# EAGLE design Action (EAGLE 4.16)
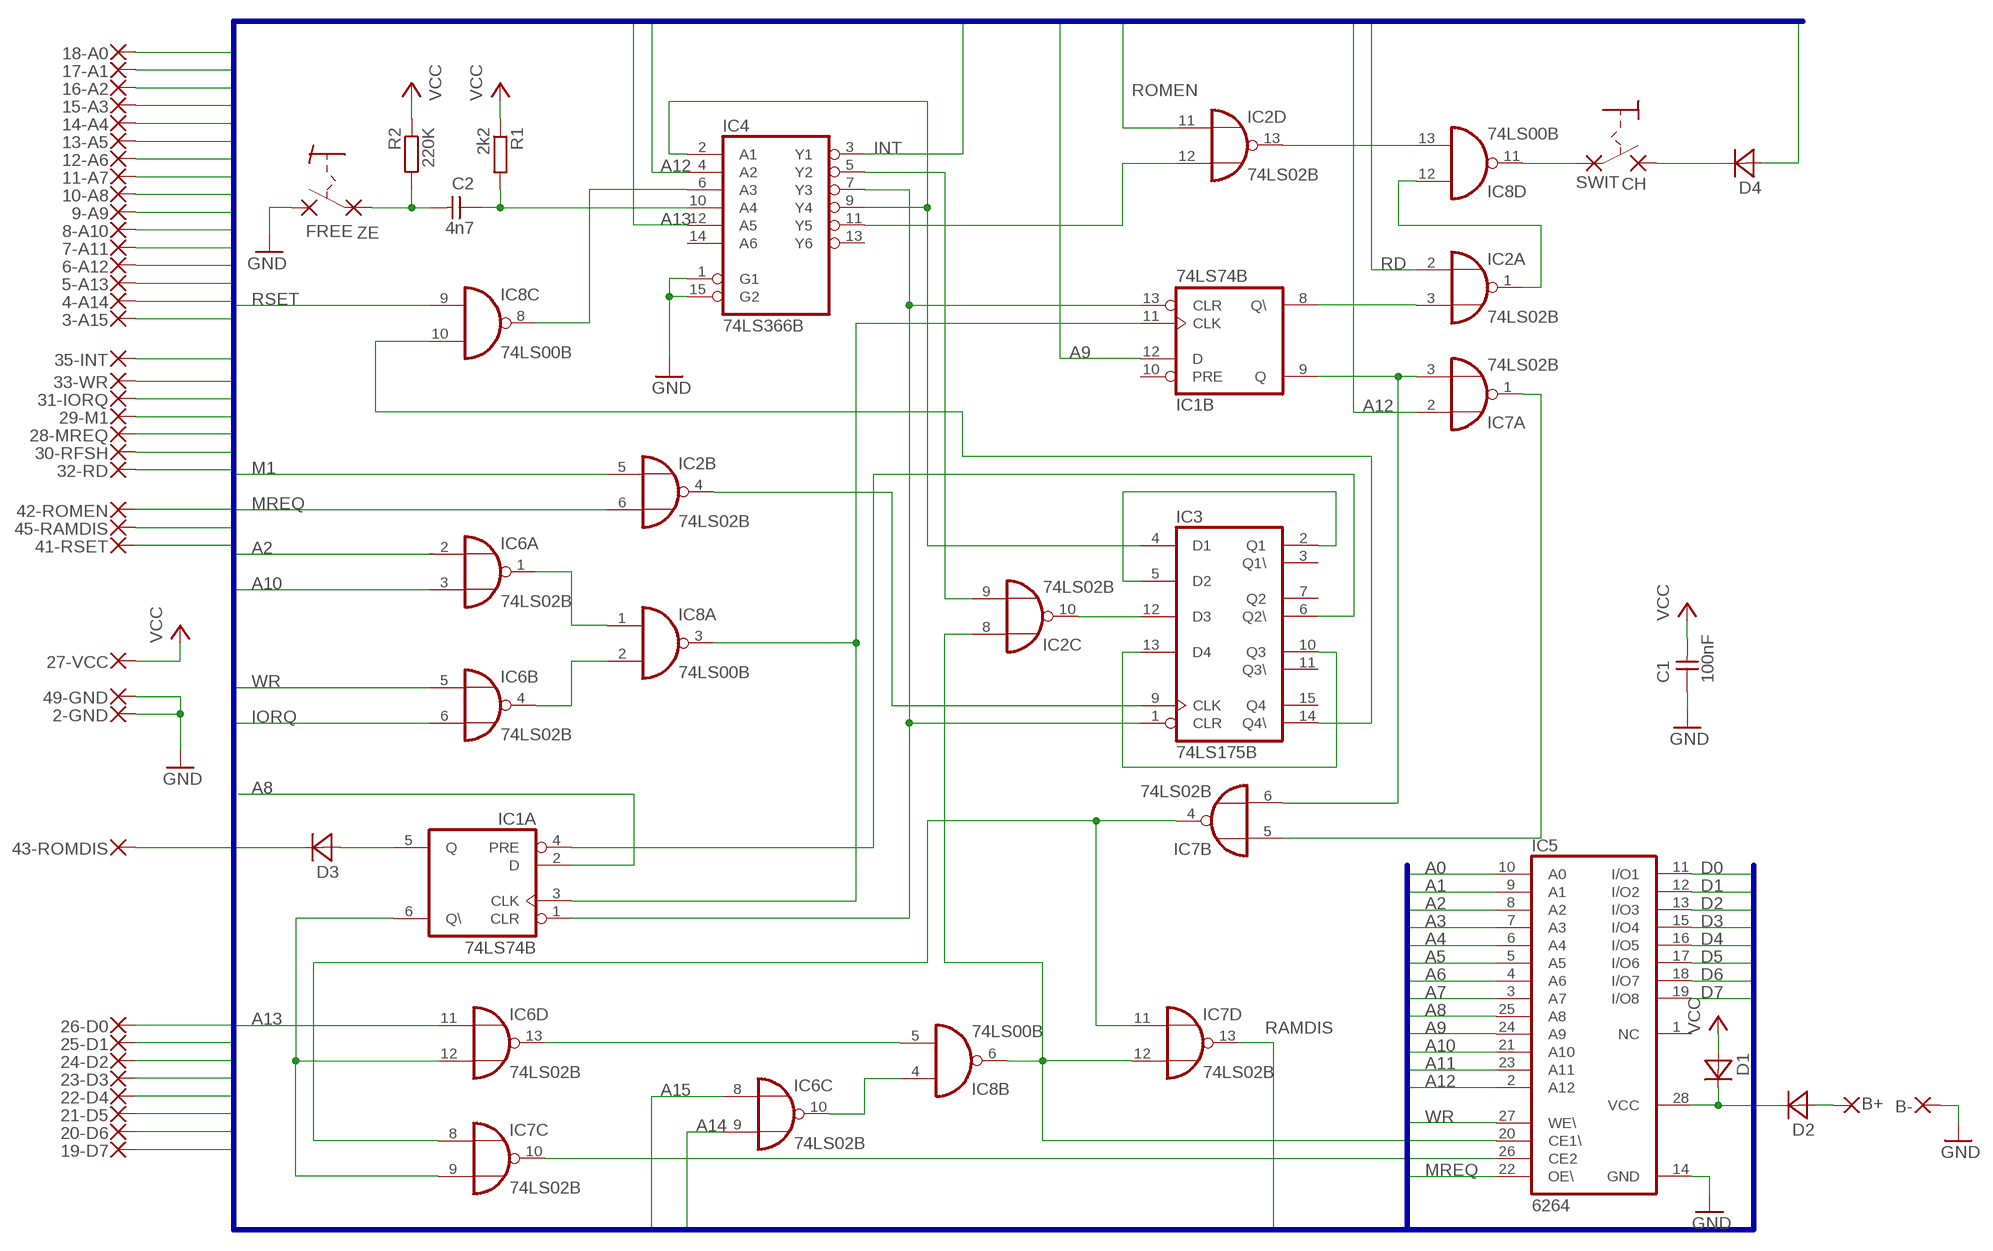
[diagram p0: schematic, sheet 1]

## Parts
2-GND  1,27-REDONDO0.8  [1,27/0,8-REDONDO]
3-A15  1,27-REDONDO0.8  [1,27/0,8-REDONDO]
4-A14  1,27-REDONDO0.8  [1,27/0,8-REDONDO]
5-A13  1,27-REDONDO0.8  [1,27/0,8-REDONDO]
6-A12  1,27-REDONDO0.8  [1,27/0,8-REDONDO]
7-A11  1,27-REDONDO0.8  [1,27/0,8-REDONDO]
8-A10  1,27-REDONDO0.8  [1,27/0,8-REDONDO]
9-A9  1,27-REDONDO0.8  [1,27/0,8-REDONDO]
10-A8  1,27-REDONDO0.8  [1,27/0,8-REDONDO]
11-A7  1,27-REDONDO0.8  [1,27/0,8-REDONDO]
12-A6  1,27-REDONDO0.8  [1,27/0,8-REDONDO]
13-A5  1,27-REDONDO0.8  [1,27/0,8-REDONDO]
14-A4  1,27-REDONDO0.8  [1,27/0,8-REDONDO]
15-A3  1,27-REDONDO0.8  [1,27/0,8-REDONDO]
16-A2  1,27-REDONDO0.8  [1,27/0,8-REDONDO]
17-A1  1,27-REDONDO0.8  [1,27/0,8-REDONDO]
18-A0  1,27-REDONDO0.8  [1,27/0,8-REDONDO]
19-D7  1,27-REDONDO0.8  [1,27/0,8-REDONDO]
20-D6  1,27-REDONDO0.8  [1,27/0,8-REDONDO]
21-D5  1,27-REDONDO0.8  [1,27/0,8-REDONDO]
22-D4  1,27-REDONDO0.8  [1,27/0,8-REDONDO]
23-D3  1,27-REDONDO0.8  [1,27/0,8-REDONDO]
24-D2  1,27-REDONDO0.8  [1,27/0,8-REDONDO]
25-D1  1,27-REDONDO0.8  [1,27/0,8-REDONDO]
26-D0  1,27-REDONDO0.8  [1,27/0,8-REDONDO]
27-VCC  1,27-REDONDO0.8  [1,27/0,8-REDONDO]
28-MREQ  1,27-REDONDO0.8  [1,27/0,8-REDONDO]
29-M1  1,27-REDONDO0.8  [1,27/0,8-REDONDO]
30-RFSH  1,27-REDONDO0.8  [1,27/0,8-REDONDO]
31-IORQ  1,27-REDONDO0.8  [1,27/0,8-REDONDO]
32-RD  1,27-REDONDO0.8  [1,27/0,8-REDONDO]
33-WR  1,27-REDONDO0.8  [1,27/0,8-REDONDO]
35-INT  1,27-REDONDO0.8  [1,27/0,8-REDONDO]
41-RSET  1,27-REDONDO0.8  [1,27/0,8-REDONDO]
42-ROMEN  1,27-REDONDO0.8  [1,27/0,8-REDONDO]
43-ROMDIS  1,27-REDONDO0.8  [1,27/0,8-REDONDO]
45-RAMDIS  1,27-REDONDO0.8  [1,27/0,8-REDONDO]
49-GND  1,27-REDONDO0.8  [1,27/0,8-REDONDO]
B+  1,27-CUADRADO0.8  [1,27/0,8-CUADRADO]
B-  1,27-CUADRADO0.8  [1,27/0,8-CUADRADO]
C1  100nF  CAPNP-10  [C-10]
C2  4n7  CAPNP-10  [C-10]
CH  1,6/0,8  [1,6/0,8]
D1  DIODE-10/2  [D-10/2]
D2  DIODE-10/2  [D-10/2]
D3  DIODE-10/2  [D-10/2]
D4  DIODE-12,5/2  [D-12,5/2]
FREE  1,6/0,8  [1,6/0,8]
IC1  74LS74B  [DIL14-B]
IC2  74LS02B  [DIL14-B]
IC3  74LS175B  [DIL16-B]
IC4  74LS366B  [DIL16-B]
IC5  6264  4364CB  [DIL28-6B]
IC6  74LS02B  [DIL14-B]
IC7  74LS02B  [DIL14-B]
IC8  74LS00B  [DIL14-B]
R1  2k2  R-EU_0207/10  [0207/10]
R2  220K  R-EU_0207/10  [0207/10]
SWIT  1,6/0,8  [1,6/0,8]
ZE  1,6/0,8  [1,6/0,8]

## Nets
A0: 18-A0.1(P) IC5.10(A0)
A1: 17-A1.1(P) IC5.9(A1)
A2: 16-A2.1(P) IC5.8(A2) IC6.2(A:I0)
A3: 15-A3.1(P) IC5.7(A3)
A4: 14-A4.1(P) IC5.6(A4)
A5: 13-A5.1(P) IC5.5(A5)
A6: 12-A6.1(P) IC5.4(A6)
A7: 11-A7.1(P) IC5.3(A7)
A8: 10-A8.1(P) IC1.2(A:D) IC5.25(A8)
A9: 9-A9.1(P) IC1.12(B:D) IC5.24(A9)
A10: 8-A10.1(P) IC5.21(A10) IC6.3(A:I1)
A11: 7-A11.1(P) IC5.23(A11)
A12: 6-A12.1(P) IC4.4(A2) IC5.2(A12) IC7.2(A:I0)
A13: 5-A13.1(P) IC4.12(A5) IC6.11(D:I0)
A14: 4-A14.1(P) IC6.9(C:I1)
A15: 3-A15.1(P) IC6.8(C:I0)
D0: 26-D0.1(P) IC5.11(I/O1)
D1: 25-D1.1(P) IC5.12(I/O2)
D2: 24-D2.1(P) IC5.13(I/O3)
D3: 23-D3.1(P) IC5.15(I/O4)
D4: 22-D4.1(P) IC5.16(I/O5)
D5: 21-D5.1(P) IC5.17(I/O6)
D6: 20-D6.1(P) D4.P$1(A) IC5.18(I/O7)
D7: 19-D7.1(P) IC5.19(I/O8)
GND: 2-GND.1(P) 49-GND.1(P) B-.P$1(P) C1.1 IC4.1(G1) IC4.15(G2) IC5.14(GND) ZE.1(P)
INT: 35-INT.1(P) IC4.3(Y1)
IORQ: 31-IORQ.1(P) IC6.6(B:I1)
M1: 29-M1.1(P) IC2.5(B:I0)
MREQ: 28-MREQ.1(P) IC2.6(B:I1) IC5.22(OE\)
N$3: IC4.6(A3) IC8.8(C:O)
N$10: IC8.11(D:O) SWIT.1(P)
N$11: IC7.4(B:O) IC7.8(C:I0) IC7.11(D:I0)
N$12: 43-ROMDIS.1(P) D3.P$4(K)
N$15: D1.P$4(K) D2.P$4(K) IC5.28(VCC)
N$16: B+.P$1(P) D2.P$3(A)
N$17: D3.P$3(A) IC1.5(A:Q)
N$20: IC2.1(A:O) IC8.12(D:I0)
N$21: IC1.8(B:Q\) IC2.3(A:I1)
N$22: IC2.4(B:O) IC3.9(CLK)
N$23: IC2.8(C:I0) IC5.20(CE1\) IC7.12(D:I1) IC8.6(B:O)
N$24: IC2.9(C:I1) IC4.5(Y2)
N$25: IC2.10(C:O) IC3.12(D3)
N$26: IC3.10(Q3) IC3.13(D4)
N$27: IC2.13(D:O) IC8.13(D:I1)
N$28: IC2.12(D:I1) IC4.11(Y5)
N$29: IC1.9(B:Q) IC7.3(A:I1) IC7.6(B:I1)
N$30: IC1.1(A:CLR) IC1.13(B:CLR) IC3.1(CLR) IC4.7(Y3)
N$31: IC1.6(A:Q\) IC6.12(D:I1) IC7.9(C:I1)
N$32: IC5.26(CE2) IC7.10(C:O)
N$33: IC1.4(A:PRE) IC3.6(Q2\)
N$34: IC1.3(A:CLK) IC1.11(B:CLK) IC8.3(A:O)
N$35: IC3.2(Q1) IC3.5(D2)
N$36: IC3.14(Q4\) IC8.10(C:I1)
N$37: IC3.4(D1) IC4.2(A1) IC4.9(Y4)
N$38: C2.1 IC4.10(A4) R1.2
N$39: IC7.1(A:O) IC7.5(B:I0)
N$40: IC6.1(A:O) IC8.1(A:I0)
N$41: IC6.4(B:O) IC8.2(A:I1)
N$42: IC6.10(C:O) IC8.4(B:I0)
N$43: IC6.13(D:O) IC8.5(B:I1)
N$44: CH.1(P) D4.P$2(K)
N$45: C2.2 FREE.1(P) R2.2
RAMDIS: 45-RAMDIS.1(P) IC7.13(D:O)
RD: 32-RD.1(P) IC2.2(A:I0)
RFSH: 30-RFSH.1(P)
ROMEN: 42-ROMEN.1(P) IC2.11(D:I0)
RSET: 41-RSET.1(P) IC8.9(C:I0)
VCC: 27-VCC.1(P) C1.2 D1.P$3(A) R1.1 R2.1
WR: 33-WR.1(P) IC5.27(WE\) IC6.5(B:I0)
Unconnected: IC1.10(B:PRE) IC3.3(Q1\) IC3.7(Q2) IC3.11(Q3\) IC3.15(Q4) IC4.13(Y6) IC4.14(A6) IC5.1(NC)

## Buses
A[0..15],RD,WR,IORQ,M1,MREQ,RFSH,D[0..7],ROMEN,INT,RAMDIS,RSET

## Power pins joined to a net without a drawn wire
GND: IC1.7(P:GND) IC2.7(P:GND) IC3.8(GND) IC4.8(GND) IC6.7(P:GND) IC7.7(P:GND) IC8.7(P:GND)
VCC: IC1.14(P:VCC) IC2.14(P:VCC) IC3.16(VCC) IC4.16(VCC) IC6.14(P:VCC) IC7.14(P:VCC) IC8.14(P:VCC)

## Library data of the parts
2-GND 3-A15 4-A14 5-A13 6-A12 7-A11 8-A10 9-A9 10-A8 11-A7 12-A6 13-A5 14-A4 15-A3 16-A2 17-A1 18-A0 19-D7 20-D6 21-D5 22-D4 23-D3 24-D2 25-D1 26-D0 27-VCC 28-MREQ 29-M1 30-RFSH 31-IORQ 32-RD 33-WR 35-INT 41-RSET 42-ROMEN 43-ROMDIS 45-RAMDIS 49-GND = wirepad2:1,27-REDONDO
B+ B- = wirepad2:1,27-CUADRADO
C1 C2 = discrete2:CAPNP-10
CH FREE SWIT ZE = wirepad:1,6/0,8: THROUGH-HOLE PAD
D1-D3 = discrete2:DIODE-10/2
D4 = discrete2:DIODE-12,5/2
IC1 = 74xx-eu2:74*74: Dual D type positive edge triggered FLIP FLOP, preset and clear
IC2 IC6 IC7 = 74xx-eu2:74*02: Quad 2-input NOR gate
IC3 = 74xx-eu2:74*175: Qadruple D type FLIP FLOP, clear
IC4 = 74xx-eu2:74*366: Hex BUS DRIVER, 3-state
IC5 = memory-nec:4364C: MEMORY
IC8 = 74xx-eu2:74*00: Quad 2-input NAND gate
R1 R2 = rcl:R-EU_: RESISTOR, European symbol

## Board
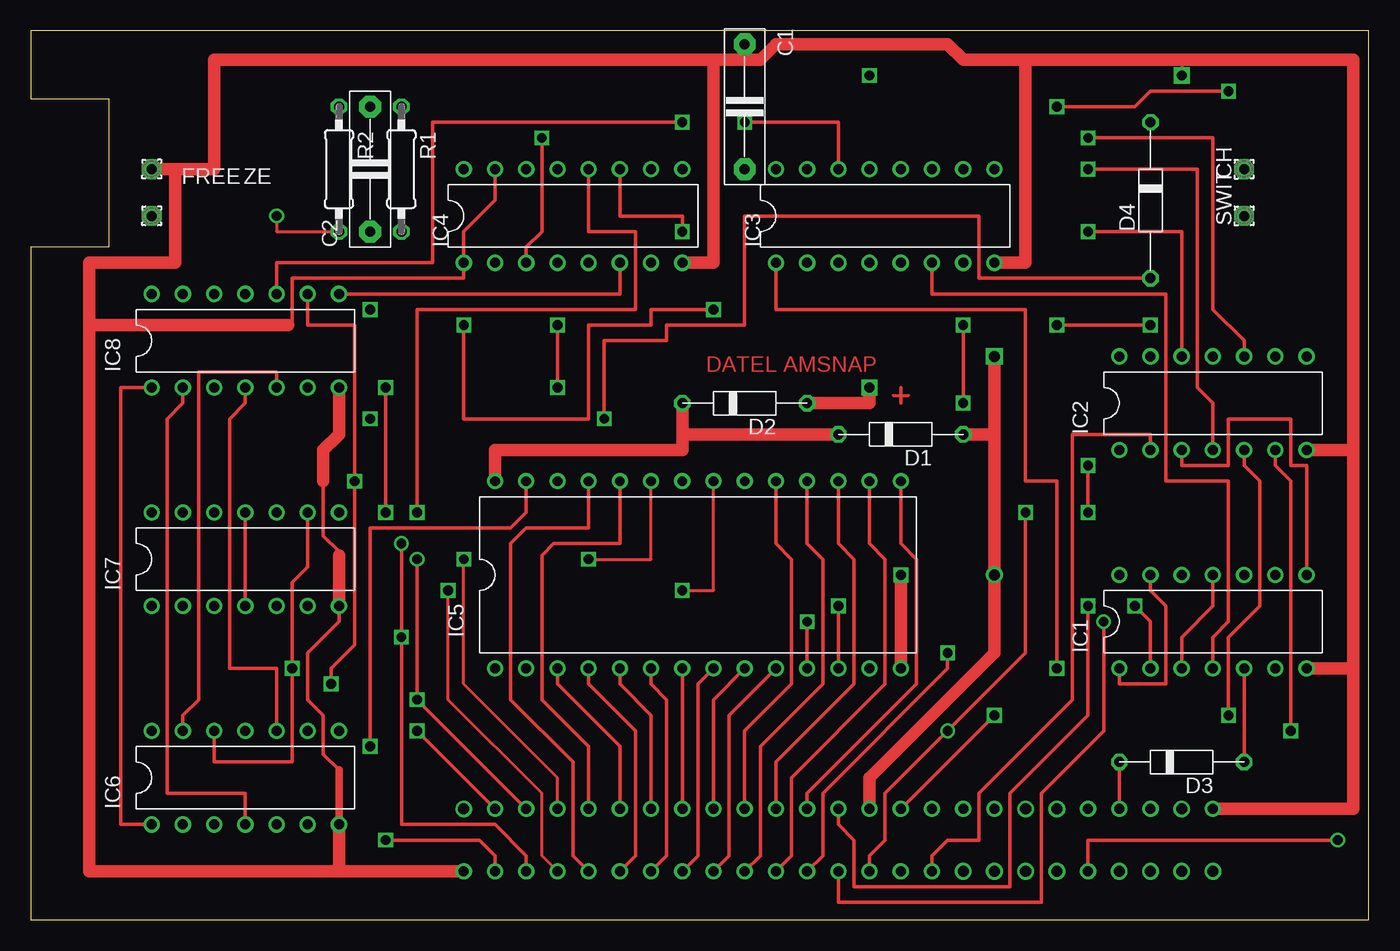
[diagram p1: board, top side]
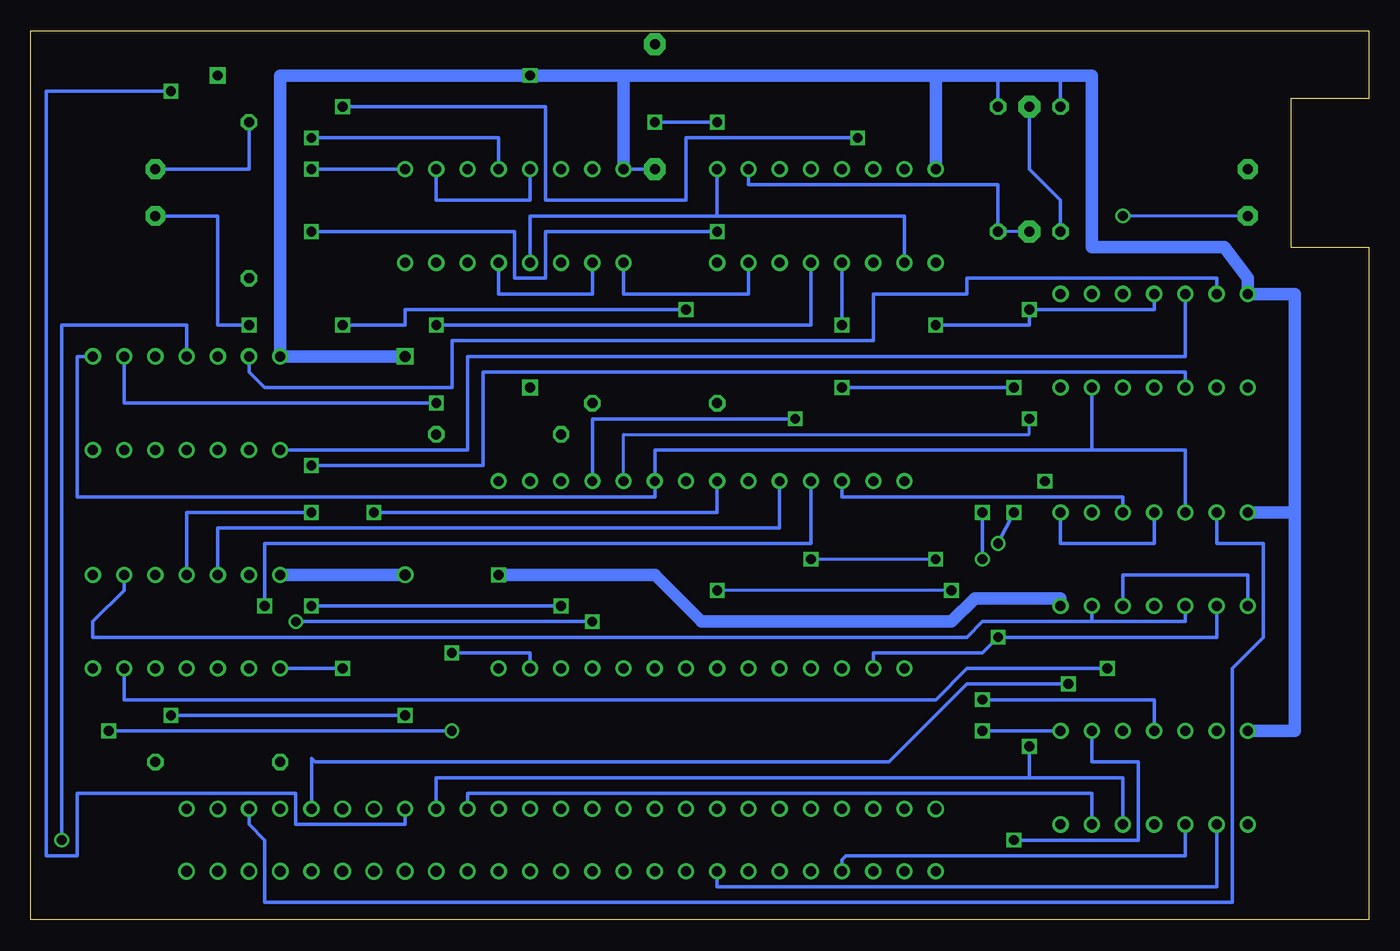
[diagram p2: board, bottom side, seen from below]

Size 108.89 x 72.38 mm. Coordinates in mm from the lower left corner, seen from the top.
Outline: 0,72.38 108.89,72.38 108.89,0 0.01,0 0,48.1 0,54.76 6.35,54.76 6.35,66.83 0,66.83 0,72.38
Outline: 0.01,72.38 0,72.38
Copper layers (1*16): Top 0.035mm / dielectric 1.5mm / Bottom 0.035mm
Design rules "default": minimum track width 10mil, minimum drill 24mil, track to track 8mil, track to pad 8mil, pad to pad 8mil, via to via 8mil, smd to smd 8mil, copper to edge 40mil, drill to drill 8mil, minimum pad ring 10mil, minimum via ring 8mil, stop-mask expansion 4mil, vias tented up to drill 0mil, thermal gap 10mil

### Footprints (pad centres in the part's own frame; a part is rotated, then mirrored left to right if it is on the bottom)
1,27/0,8-REDONDO = drill 0.813 pad 1.27 round: 1 0,0
1,27/0,8-CUADRADO = drill 0.8 pad 1.27 square: P$1 0,0
C-10 = drill 0.813 pad 1.778 octagon: 1 -5.08,0; 2 5.08,0
1,6/0,8 = drill 0.813 pad 1.6 octagon: 1 0,0
D-10/2 = drill 0.813 octagon: P$3 -5.08,0; P$4 5.08,0
D-12,5/2 = drill 0.813 octagon: P$1 -6.35,0; P$2 6.35,0
DIL14-B = drill 0.813 round: 1 -7.62,-3.81; 2 -5.08,-3.81; 3 -2.54,-3.81; 4 0,-3.81; 5 2.54,-3.81; 6 5.08,-3.81; 7 7.62,-3.81; 8 7.62,3.81; 9 5.08,3.81; 10 2.54,3.81; 11 0,3.81; 12 -2.54,3.81; 13 -5.08,3.81; 14 -7.62,3.81
DIL16-B = drill 0.813 round: 1 -8.89,-3.81; 2 -6.35,-3.81; 3 -3.81,-3.81; 4 -1.27,-3.81; 5 1.27,-3.81; 6 3.81,-3.81; 7 6.35,-3.81; 8 8.89,-3.81; 9 8.89,3.81; 10 6.35,3.81; 11 3.81,3.81; 12 1.27,3.81; 13 -1.27,3.81; 14 -3.81,3.81; 15 -6.35,3.81; 16 -8.89,3.81
DIL28-6B = drill 0.8 round: 1 -16.51,-7.62; 2 -13.97,-7.62; 3 -11.43,-7.62; 4 -8.89,-7.62; 5 -6.35,-7.62; 6 -3.81,-7.62; 7 -1.27,-7.62; 8 1.27,-7.62; 9 3.81,-7.62; 10 6.35,-7.62; 11 8.89,-7.62; 12 11.43,-7.62; 13 13.97,-7.62; 14 16.51,-7.62; 15 16.51,7.62; 16 13.97,7.62; 17 11.43,7.62; 18 8.89,7.62; 19 6.35,7.62; 20 3.81,7.62; 21 1.27,7.62; 22 -1.27,7.62; 23 -3.81,7.62; 24 -6.35,7.62; 25 -8.89,7.62; 26 -11.43,7.62; 27 -13.97,7.62; 28 -16.51,7.62
0207/10 = drill 0.813 octagon: 1 -5.08,0; 2 5.08,0

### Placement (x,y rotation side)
2-GND  35.24,3.96 90 top
3-A15  37.78,9.04 0 top
4-A14  37.78,3.96 180 top
5-A13  40.32,9.04 0 top
6-A12  40.32,3.96 180 top
7-A11  42.86,9.04 0 top
8-A10  42.86,3.96 180 top
9-A9  45.4,9.04 0 top
10-A8  45.4,3.96 180 top
11-A7  47.94,9.04 0 top
12-A6  47.94,3.96 180 top
13-A5  50.48,9.04 0 top
14-A4  50.48,3.96 180 top
15-A3  53.02,9.04 0 top
16-A2  53.02,3.96 180 top
17-A1  55.56,9.04 0 top
18-A0  55.56,3.96 180 top
19-D7  58.1,9.04 0 top
20-D6  58.1,3.96 180 top
21-D5  60.64,9.04 0 top
22-D4  60.64,3.96 180 top
23-D3  63.18,9.04 0 top
24-D2  63.18,3.96 180 top
25-D1  65.72,9.04 0 top
26-D0  65.72,3.96 180 top
27-VCC  68.26,9.04 0 top
28-MREQ  68.26,3.96 180 top
29-M1  70.8,9.04 0 top
30-RFSH  70.8,3.96 180 top
31-IORQ  73.34,9.04 0 top
32-RD  73.34,3.96 180 top
33-WR  75.88,9.04 0 top
35-INT  78.42,9.04 0 top
41-RSET  86.04,9.04 0 top
42-ROMEN  86.04,3.96 180 top
43-ROMDIS  88.58,9.04 0 top
45-RAMDIS  91.12,9.04 0 top
49-GND  96.2,9.04 0 top
B+  68.26,43.33 270 top
B-  93.66,68.73 270 top
C1  58.1,66.19 270 top
C2  27.62,61.11 90 top
CH  98.74,61.11 90 top
D1  70.8,39.52 180 top
D2  58.1,42.06 180 top
D3  93.66,12.85 180 top
D4  91.12,58.57 90 top
FREE  9.84,57.3 0 top
IC1  96.2,24.28 0 top
IC2  96.2,42.06 0 top
IC3  69.53,57.3 0 top
IC4  44.13,57.3 0 top
IC5  54.29,28.09 0 top
IC6  17.46,11.58 0 top
IC7  17.46,29.36 0 top
IC8  17.46,47.14 0 top
R1  30.16,61.11 270 top
R2  25.08,61.11 270 top
SWIT  98.74,57.3 90 top
ZE  9.84,61.11 0 top

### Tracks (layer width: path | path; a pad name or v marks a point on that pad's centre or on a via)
A0
  Top 0.305: IC5.10 56.83,16.66 56.83,5.23 18-A0.1
A1
  Top 0.305: IC5.9 55.56,17.93 17-A1.1
A2
  Top 0.305: IC5.8 54.29,19.2 54.29,5.23 16-A2.1 53.02,3.65
  Bottom 0.305: IC6.2 12.38,2.69 53.02,2.69 16-A2.1
A3
  Top 0.305: 15-A3.1 IC5.7
A4
  Top 0.305: IC5.6 50.48,19.2 51.75,17.93 51.75,5.23 14-A4.1 | 14-A4.1 50.8,3.96 50.48,4.28 14-A4.1
A5
  Top 0.305: IC5.5 47.94,19.2 50.48,16.66 13-A5.1
A6
  Top 0.305: IC5.4 45.4,19.2 49.21,15.39 49.21,5.23 12-A6.1
A7
  Top 0.305: IC5.3 42.86,19.2 47.94,14.12 11-A7.1
A8  (via drill 0.8)
  Top 0.305: 10-A8.1 44.13,5.23 44.13,12.85 39.05,17.93 39.05,30.63 40.32,31.9 45.4,31.9 IC5.25 | IC1.2 91.12,24.28 v89.85,25.55
  Bottom 0.305: v89.85,25.55 89.85,30.63 45.4,30.63 IC5.25
A9
  Top 0.305: 9-A9.1 45.4,14.12 41.59,17.93 41.59,29.68 42.54,30.63 47.94,30.63 IC5.24
  Bottom 0.305: IC1.12 93.66,31.9 47.94,31.9 IC5.24
A10  (via drill 0.8)
  Top 0.254: 8-A10.1 41.59,5.23 41.59,10.31 33.97,17.93 v33.97,26.82 | v53.02,26.82 55.56,26.82 IC5.21
  Bottom 0.254: v33.97,26.82 v53.02,26.82
  Bottom 0.305: 8-A10.1 42.86,4.92 42.54,5.23 14.92,5.23 IC6.3
A11  (via drill 0.8)
  Top 0.254: 7-A11.1 42.86,11.58 35.24,19.2 v35.24,29.36 | v45.4,29.36 50.48,29.36 IC5.23
  Bottom 0.254: v35.24,29.36 v45.4,29.36
A12  (via drill 0.8, 0.8 pad 0.81)
  Top 0.305: 6-A12.1 40.32,5.23 37.78,7.77 30.16,7.77 v30.16,23.01 v30.16,30.63 | v42.86,43.33 v42.86,48.41 | v28.89,33.17 v28.89,43.33
  Bottom 0.305: IC7.2 12.38,23.01 v30.16,23.01 31.43,21.74 40.32,21.74 IC5.2 | v42.86,48.41 IC4.4 | v28.89,43.33 v42.86,43.33 | v30.16,30.63 v28.89,33.17
A13  (via drill 0.8, 0.8 pad 0.81)
  Top 0.305: 5-A13.1 v31.43,17.93 v31.43,29.36 | v31.43,33.17 31.43,49.68 49.21,49.68 49.21,56.03 45.4,56.03 IC4.12
  Bottom 0.305: v31.43,17.93 17.46,17.93 IC6.11 | v31.43,29.36 v31.43,33.17
A14  (via drill 0.8)
  Top 0.305: 4-A14.1 37.78,5.23 36.51,6.5 v28.89,6.5
  Bottom 0.305: v28.89,6.5 18.73,6.5 18.73,12.85 22.54,12.85 IC6.9
A15  (via drill 0.8)
  Top 0.305: v31.43,15.39 3-A15.1
  Bottom 0.305: IC6.8 v31.43,15.39
D0  (via drill 0.8 pad 1.02)
  Top 0.305: 26-D0.1 65.72,1.42 82.23,1.42 82.23,10.31 87.31,15.39 v87.31,24.28 | v63.18,24.28 IC5.11
  Bottom 0.305: v87.31,24.28 v63.18,24.28
D1  (via drill 0.8 pad 1.02)
  Top 0.305: 25-D1.1 65.72,7.77 66.99,6.5 66.99,2.69 79.69,2.69 79.69,10.31 86.04,16.66 v86.04,25.55 | v65.72,25.55 IC5.12
  Bottom 0.305: v86.04,25.55 v65.72,25.55
D2  (via drill 0.8)
  Top 0.305: 24-D2.1 64.45,5.23 64.45,10.31 74.61,20.47 v74.61,21.74
  Bottom 0.305: v74.61,21.74 68.26,21.74 IC5.13
D3
  Top 0.305: IC5.15 70.8,30.63 72.07,29.36 72.07,19.2 63.18,10.31 23-D3.1
D4
  Top 0.305: IC5.16 68.26,30.63 69.53,29.36 69.53,19.2 61.91,11.58 61.91,5.23 22-D4.1
D5
  Top 0.305: IC5.17 65.72,30.63 66.99,29.36 66.99,19.2 60.64,12.85 21-D5.1
D6  (via drill 0.8)
  Top 0.305: IC5.18 63.18,30.63 64.45,29.36 64.45,19.2 59.37,14.12 59.37,5.23 20-D6.1 | D4.P$1 77.15,52.22 77.15,57.3 58.1,57.3 58.1,48.41 51.75,48.41 51.75,47.14 46.67,47.14 v46.67,40.79
  Bottom 0.305: v46.67,40.79 63.18,40.79 IC5.18
D7  (via drill 0.8)
  Top 0.305: IC5.19 60.64,30.63 61.91,29.36 61.91,19.2 58.1,15.39 19-D7.1 58.1,8.72
  Bottom 0.254: IC5.19 60.64,39.52 27.62,39.52 v27.62,40.79
GND  (via drill 0.8)
  Top 0.254: 93.66,70 B-.P$1
  Top 0.305: IC7.7 25.08,24.28 22.54,21.74 22.54,17.93 23.81,16.66 23.81,13.49 25.08,12.22 | 23.81,35.71 23.81,31.27 25.08,30 25.08,29.68 | 20.96,48.41 21.27,48.41 21.27,52.22 35.24,52.22 IC4.1 35.24,56.03 37.78,58.57 IC4.15
  Top 0.61: IC6.7 25.08,12.22
  Top 1.016: 25.08,3.96 4.76,3.96 4.76,48.41 | 25.08,3.96 2-GND.1 | 25.08,3.96 IC6.7 | 49-GND.1 107.63,9.04 107.63,20.47 | 107.63,20.47 IC1.7 | 107.63,38.25 IC2.7 | 107.63,38.25 107.63,20.47 | 107.63,38.25 107.63,70 93.66,70 80.96,70 | 80.96,70 75.88,70 74.61,71.27 60.64,71.27 59.37,70 58.1,70 | 55.56,70 14.92,70 14.92,61.11 11.75,61.11 | 55.56,70 58.1,70 | 11.75,61.11 11.75,53.49 4.76,53.49 4.76,48.41 | IC8.7 25.08,39.52 23.81,38.25 23.81,35.71 | IC7.7 25.08,29.68 | IC4.8 55.56,53.49 55.56,70 | IC3.8 80.96,53.49 80.96,70 | v70.8,28.09 IC5.14 | 4.76,48.41 20.96,48.41 | 11.75,61.11 ZE.1 | 58.1,70 C1.1
  Bottom 1.016: v70.8,28.09 58.1,28.09 54.29,24.28 33.97,24.28 32.07,26.19 25.08,26.19 IC7.7
INT  (via drill 0.8)
  Top 0.305: v97.47,67.46 91.12,67.46 89.85,66.19 v83.5,66.19 | v41.59,63.65 41.59,56.03 40.32,54.76 IC4.3
  Bottom 0.305: 35-INT.1 78.42,7.77 87.31,7.77 87.31,10.31 105.09,10.31 105.09,5.23 107.63,5.23 107.63,67.46 v97.47,67.46 | v83.5,66.19 66.99,66.19 66.99,58.57 55.56,58.57 55.56,63.65 v41.59,63.65
IORQ
  Bottom 0.305: 31-IORQ.1 73.34,10.31 22.54,10.31 IC6.6
M1  (via drill 0.8 pad 1.02)
  Top 0.305: IC2.5 98.74,36.98 100.01,35.71 100.01,25.55 97.47,23.01 v97.47,16.66 | 29-M1.1 v78.42,16.66
  Bottom 0.305: v78.42,16.66 v97.47,16.66
MREQ  (via drill 0.8 pad 1.02)
  Top 0.305: IC2.6 101.28,36.98 102.55,35.71 v102.55,15.39 | 28-MREQ.1 68.26,5.23 69.53,6.5 69.53,10.31 v74.61,15.39 80.96,21.74 v80.96,33.17
  Bottom 0.305: v74.61,15.39 v102.55,15.39 | IC5.22 53.02,33.17 v80.96,33.17
N$1  (via drill 0.9)
  other vias: 35.24,9.04
N$2  (via drill 0.9)
  other vias: 75.88,3.96
N$3
  Top 0.305: IC8.8 47.94,50.95 IC4.6
N$4  (via drill 0.9)
  other vias: 80.96,9.04
N$5  (via drill 0.9)
  other vias: 83.5,9.04
N$6  (via drill 0.9)
  other vias: 78.42,3.96
N$7  (via drill 0.9)
  other vias: 80.96,3.96
N$8  (via drill 0.9)
  other vias: 83.5,3.96
N$9  (via drill 0.9)
  other vias: 88.58,3.96
N$10  (via drill 0.8)
  Top 0.305: v83.5,48.41 v91.12,48.41 | v55.56,49.68 50.48,49.68 50.48,48.41 45.4,48.41 45.4,40.79 35.24,40.79 v35.24,48.41
  Bottom 0.305: SWIT.1 93.66,57.3 93.66,48.41 v91.12,48.41 | v83.5,48.41 78.42,48.41 78.42,49.68 v55.56,49.68 | v35.24,48.41 27.62,48.41 v27.62,49.68 17.46,49.68 IC8.11
N$11
  Top 0.305: IC7.4 IC7.11
  Bottom 0.305: IC7.8 25.08,30.63 17.46,30.63 IC7.11
N$12
  Top 0.305: 43-ROMDIS.1 D3.P$4
N$13  (via drill 0.9)
  other vias: 91.12,3.96
N$14  (via drill 0.9)
  other vias: 96.2,3.96
N$15
  Top 1.016: 53.02,39.52 D1.P$4 | 53.02,39.52 53.02,38.25 37.78,38.25 IC5.28 | 53.02,39.52 D2.P$4
N$16
  Top 1.016: D2.P$3 68.26,42.06 B+.P$1
N$17
  Top 0.305: D3.P$3 IC1.5
N$18  (via drill 0.9)
  other vias: 93.66,9.04
N$19  (via drill 0.9)
  other vias: 93.66,3.96
N$20
  Bottom 0.305: IC2.1 73.34,38.25 73.34,45.87 14.92,45.87 IC8.12
N$21
  Top 0.305: IC2.3 93.66,36.98 97.47,36.98 97.47,40.79 102.55,40.79 102.55,36.98 103.82,36.98 IC1.8
N$22  (via drill 0.8 pad 1.02)
  Top 0.305: IC2.4 96.2,42.06 94.93,43.33 94.93,61.11 v86.04,61.11
  Bottom 0.305: v86.04,61.11 IC3.9
N$23
  Bottom 0.305: IC2.8 105.09,45.87 105.09,34.44 58.1,34.44 IC5.20 58.1,38.25 22.54,38.25 | 22.54,38.25 IC8.6 | IC7.12 14.92,38.25 22.54,38.25
N$24  (via drill 0.8 pad 1.02)
  Top 0.305: v75.88,48.41 v75.88,42.06
  Bottom 0.305: IC2.9 101.28,42.06 v75.88,42.06 | v75.88,48.41 45.4,48.41 IC4.5
N$25  (via drill 0.8 pad 1.02)
  Top 0.305: IC2.10 98.74,47.14 96.2,49.68 96.2,63.65 v86.04,63.65
  Bottom 0.305: v86.04,63.65 70.8,63.65 IC3.12
N$26
  Bottom 0.305: IC3.10 75.88,58.57 68.26,58.57 IC3.13
N$27
  Bottom 0.305: IC2.13 91.12,44.6 89.85,43.33 74.61,43.33 74.61,47.14 40.32,47.14 40.32,50.95 32.7,50.95 32.7,52.22 12.38,52.22 IC8.13
N$28  (via drill 0.8 pad 1.02)
  Top 0.305: IC2.12 93.66,56.03 v86.04,56.03 | v53.02,56.03 53.02,57.3 47.94,57.3 IC4.11
  Bottom 0.305: v86.04,56.03 69.53,56.03 69.53,52.22 66.99,52.22 66.99,56.03 v53.02,56.03
N$29
  Bottom 0.305: 22.54,24.28 14.92,24.28 IC7.3 | 22.54,24.28 31.43,24.28 32.7,23.01 103.82,23.01 103.82,24.28 101.28,26.82 IC1.9 | 22.54,24.28 IC7.6
N$30  (via drill 0.8)
  Top 0.305: IC1.1 88.58,19.2 92.39,19.2 92.39,25.55 91.12,26.82 IC1.13 | v83.5,20.47 83.5,35.71 80.96,35.71 80.96,49.68 60.64,49.68 IC3.1
  Bottom 0.305: v83.5,20.47 IC1.1 | IC4.7 50.48,50.95 60.64,50.95 IC3.1
N$31  (via drill 0.8)
  Top 0.305: IC6.12 14.92,12.85 21.27,12.85 v21.27,20.47 21.27,27.46 22.54,28.73 IC7.9
  Bottom 0.305: IC1.6 101.28,17.93 35.24,17.93 32.7,20.47 v21.27,20.47
N$32
  Bottom 0.305: IC5.26 42.86,34.44 20,34.44 IC7.10
N$33
  Top 0.305: IC1.4 96.2,23.01 97.47,24.28 97.47,35.71 92.39,35.71 92.39,50.95 73.34,50.95 IC3.6
N$34  (via drill 0.8)
  Top 0.305: IC1.3 93.66,23.01 96.2,25.55 IC1.11 | v86.04,36.98 v86.04,33.17
  Bottom 0.305: IC8.3 14.92,44.6 72.07,44.6 72.07,36.98 v86.04,36.98 | v86.04,33.17 96.2,33.17 IC1.11
N$35
  Bottom 0.305: IC3.2 63.18,50.95 70.8,50.95 IC3.5
N$36  (via drill 0.8)
  Top 0.305: IC8.10 20,53.49 32.7,53.49 32.7,64.92 v53.02,64.92 | v58.1,64.92 65.72,64.92 IC3.14
  Bottom 0.305: v53.02,64.92 v58.1,64.92
N$37
  Bottom 0.305: IC3.4 68.26,57.3 53.02,57.3 | 53.02,57.3 IC4.9 | IC4.2 37.78,57.3 53.02,57.3
N$38
  Bottom 0.254: C2.1 R1.2
  Bottom 0.305: IC4.10 50.48,59.84 30.16,59.84 R1.2
N$39
  Bottom 0.305: IC7.1 9.84,28.09 20,28.09 IC7.5
N$40
  Top 0.305: IC6.1 7.3,7.77 7.3,43.33 IC8.1
N$41
  Top 0.305: IC6.4 17.46,10.31 11.11,10.31 11.11,40.79 12.38,42.06 IC8.2
N$42
  Top 0.305: IC6.10 20,20.47 16.19,20.47 16.19,40.79 17.46,42.06 IC8.4
N$43
  Top 0.305: IC6.13 12.38,16.66 13.65,17.93 13.65,44.6 20,44.6 IC8.5
N$44
  Bottom 0.305: CH.1 91.12,61.11 D4.P$2
N$45  (via drill 0.8)
  Top 0.254: v20,57.3 20,56.03 R2.2
  Bottom 0.254: FREE.1 v20,57.3
  Bottom 0.305: R2.2 25.08,58.57 27.62,61.11 C2.2
N$47
  Top 0.254: 70.17,42.7 70.8,42.7 71.44,42.7
  Top 0.305: 70.8,43.33 70.8,42.7 70.8,42.06
RAMDIS
  Bottom 0.305: 45-RAMDIS.1 91.12,7.77 89.85,6.5 89.85,1.42 11.11,1.42 11.11,20.47 8.57,23.01 8.57,30.63 12.38,30.63 IC7.13
RD
  Top 0.305: 32-RD.1 73.34,5.23 74.61,6.5 77.15,6.5 77.15,10.31 84.77,17.93 84.77,39.52 91.12,39.52 IC2.2
ROMEN  (via drill 0.8)
  Top 0.305: 42-ROMEN.1 86.04,6.5 v106.36,6.5
  Bottom 0.305: v106.36,6.5 106.36,48.41 96.2,48.41 IC2.11
RSET  (via drill 0.8)
  Top 0.305: IC8.9 22.54,48.41 26.35,48.41 v26.35,35.71 26.35,22.38 24.45,20.47 v24.45,19.2
  Bottom 0.305: v24.45,19.2 32.7,19.2 39.05,12.85 85.73,12.85 86.04,13.17 41-RSET.1
VCC  (via drill 0.8, 0.9)
  Top 1.016: 27-VCC.1 68.26,11.58 78.42,21.74 v78.42,28.09 78.42,39.52 | v78.42,45.87 78.42,39.52 | 78.42,39.52 D1.P$3
  Bottom 0.305: 30.16,68.73 R1.1 | 25.08,68.73 R2.1 | IC3.16 C1.2
  Bottom 1.016: v78.42,45.87 IC2.14 88.58,68.73 v68.26,68.73 60.64,68.73 | 35.24,68.73 60.64,68.73 | 35.24,68.73 30.16,68.73 25.08,68.73 22.54,68.73 22.54,54.76 11.75,54.76 9.84,52.22 IC8.14 6.03,50.95 6.03,33.17 | 60.64,68.73 IC3.16 | 35.24,68.73 IC4.16 | 6.03,33.17 6.03,15.39 IC6.14 | 6.03,33.17 IC7.14 | v78.42,28.09 IC1.14
WR  (via drill 0.8)
  Top 0.305: IC5.27 40.32,33.17 39.05,31.9 27.62,31.9 v27.62,14.12
  Bottom 0.305: 33-WR.1 75.88,11.58 27.62,11.58 | 27.62,11.58 20,11.58 IC6.5 | 27.62,11.58 v27.62,14.12

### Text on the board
Top: DATEL AMSNAP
